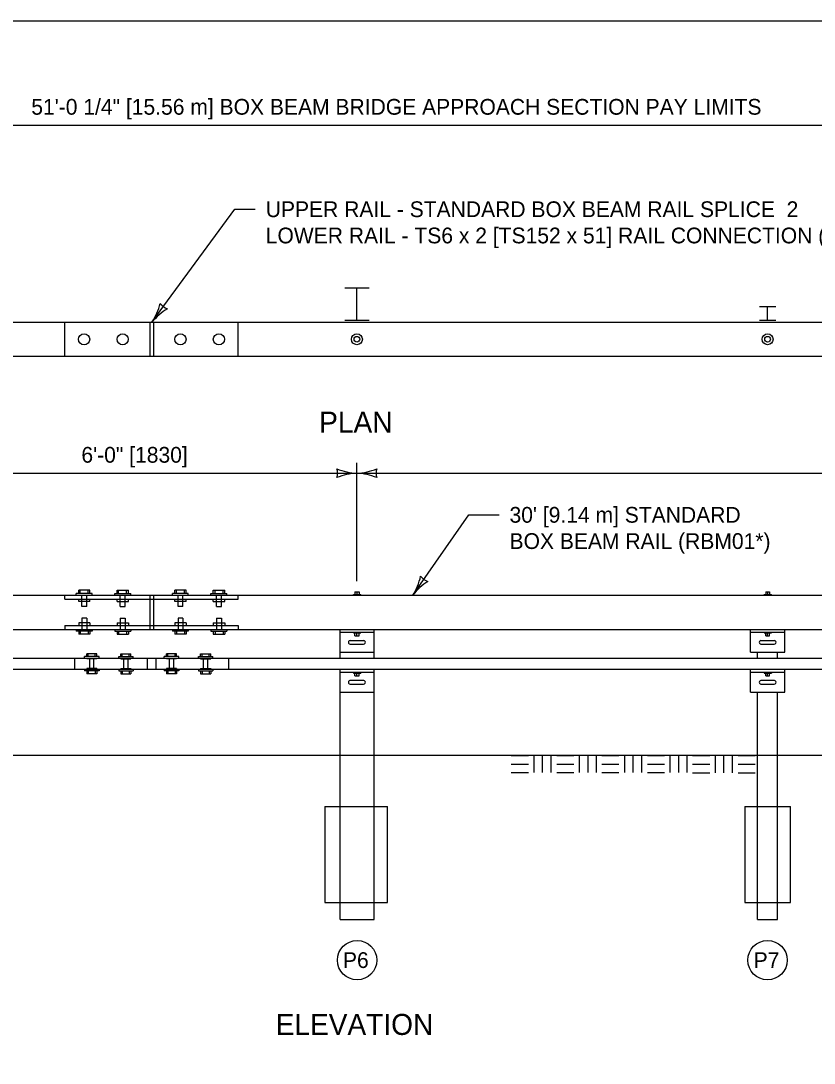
# Model space of a CAD drawing. Extents: x 49991.4 to 50021, y 49987.6 to 50011.4.
# Drawn here: x 50006.567 to 50009.589, y 49995.029 to 49998.999 of the extents above; entities that cross this region are included whole.
import ezdxf

# ---------------------------------------------------------------- set-up
doc = ezdxf.new("R2010")
doc.units = 0
for name, color, linetype in [('Level 1', 7, 'Continuous'), ('Level 2', 7, 'Continuous'), ('Level 3', 7, 'Continuous'), ('Level 4', 7, 'Continuous')]:
    doc.layers.add(name, color=color, linetype=linetype)

msp = doc.modelspace()

# ---------------------------------------------------------------- linework, layer by layer
at = {"layer": 'Level 1'}
for p, q in [((50007.8006, 49997.982), (50007.8938, 49997.982)), ((50007.8468, 49997.8587), (50007.8468, 49997.982)), ((50009.381, 49997.9109), (50009.4424, 49997.9109)), ((50009.4113, 49997.8587), (50009.4113, 49997.9109)), ((50001.743, 49997.8514), (50015.4519, 49997.8514)), ((50007.0582, 49997.8514), (50007.0582, 49997.7218)), ((50007.0716, 49997.8514), (50007.0716, 49997.7218)), ((50007.8006, 49997.8587), (50007.8938, 49997.8587)), ((50009.381, 49997.8587), (50009.4424, 49997.8587)), ((50001.743, 49997.7218), (50015.4519, 49997.7218)), ((50006.83, 49996.8312), (50006.7875, 49996.8312)), ((50006.7875, 49996.8181), (50006.7875, 49996.8312)), ((50006.7928, 49996.8181), (50006.7928, 49996.8312)), ((50006.8229, 49996.8181), (50006.8229, 49996.8312)), ((50006.83, 49996.8181), (50006.83, 49996.8312)), ((50006.9339, 49996.8312), (50006.9765, 49996.8312)), ((50006.9339, 49996.8181), (50006.9339, 49996.8312)), ((50006.9394, 49996.8181), (50006.9394, 49996.8312)), ((50006.9695, 49996.8181), (50006.9695, 49996.8312)), ((50006.9765, 49996.8181), (50006.9765, 49996.8312)), ((50007.1969, 49996.8312), (50007.1533, 49996.8312)), ((50007.1533, 49996.8181), (50007.1533, 49996.8312)), ((50007.1595, 49996.8181), (50007.1595, 49996.8312)), ((50007.1904, 49996.8181), (50007.1904, 49996.8312)), ((50007.1969, 49996.8181), (50007.1969, 49996.8312)), ((50007.2998, 49996.8181), (50007.2998, 49996.8312)), ((50007.2998, 49996.8312), (50007.3433, 49996.8312)), ((50007.3069, 49996.8181), (50007.3069, 49996.8312)), ((50007.337, 49996.8181), (50007.337, 49996.8312)), ((50007.3433, 49996.8181), (50007.3433, 49996.8312)), ((50002.0298, 49996.8116), (50015.4519, 49996.8116)), ((50006.8388, 49996.8181), (50006.7777, 49996.8181)), ((50006.7777, 49996.8116), (50006.7777, 49996.8181)), ((50006.8388, 49996.8116), (50006.8388, 49996.8181)), ((50006.9243, 49996.8181), (50006.9854, 49996.8181)), ((50006.9243, 49996.8116), (50006.9243, 49996.8181)), ((50006.9854, 49996.8116), (50006.9854, 49996.8181)), ((50007.0582, 49996.8126), (50007.0582, 49996.6812)), ((50007.0716, 49996.8126), (50007.0716, 49996.6812)), ((50007.2048, 49996.8181), (50007.1444, 49996.8181)), ((50007.1444, 49996.8116), (50007.1444, 49996.8181)), ((50007.2048, 49996.8116), (50007.2048, 49996.8181)), ((50007.2908, 49996.8181), (50007.3513, 49996.8181)), ((50007.2908, 49996.8126), (50007.2908, 49996.8181)), ((50007.3513, 49996.8116), (50007.3513, 49996.8181)), ((50007.7828, 49996.8116), (50007.9124, 49996.8116)), ((50007.8334, 49996.8144), (50007.8619, 49996.8144)), ((50007.8334, 49996.8116), (50007.8334, 49996.8144)), ((50007.8387, 49996.825), (50007.8556, 49996.825)), ((50007.8387, 49996.825), (50007.8387, 49996.8144)), ((50007.8468, 49996.825), (50007.8468, 49996.8144)), ((50007.8556, 49996.825), (50007.8556, 49996.8144)), ((50007.8619, 49996.8116), (50007.8619, 49996.8144)), ((50009.3793, 49996.8116), (50009.4441, 49996.8116)), ((50009.3981, 49996.8144), (50009.4266, 49996.8144)), ((50009.3981, 49996.8116), (50009.3981, 49996.8144)), ((50009.4041, 49996.825), (50009.4192, 49996.825)), ((50009.4041, 49996.825), (50009.4041, 49996.8144)), ((50009.4113, 49996.825), (50009.4113, 49996.8144)), ((50009.4192, 49996.825), (50009.4192, 49996.8144)), ((50009.4266, 49996.8116), (50009.4266, 49996.8144)), ((50002.0298, 49996.6812), (50015.4519, 49996.6812)), ((50006.7777, 49996.6812), (50006.7777, 49996.675)), ((50006.8388, 49996.675), (50006.7777, 49996.675)), ((50006.7875, 49996.675), (50006.7875, 49996.6634)), ((50006.7928, 49996.675), (50006.7928, 49996.6634)), ((50006.8229, 49996.675), (50006.8229, 49996.6634)), ((50006.83, 49996.675), (50006.83, 49996.6634)), ((50006.8388, 49996.6812), (50006.8388, 49996.675)), ((50006.9243, 49996.6812), (50006.9243, 49996.675)), ((50006.9243, 49996.675), (50006.9854, 49996.675)), ((50006.9339, 49996.675), (50006.9339, 49996.6634)), ((50006.9394, 49996.675), (50006.9394, 49996.6634)), ((50006.9695, 49996.675), (50006.9695, 49996.6634)), ((50006.9765, 49996.675), (50006.9765, 49996.6634)), ((50006.9854, 49996.6812), (50006.9854, 49996.675)), ((50007.1444, 49996.6812), (50007.1444, 49996.675)), ((50007.2048, 49996.675), (50007.1444, 49996.675)), ((50007.1533, 49996.675), (50007.1533, 49996.6634)), ((50007.1595, 49996.675), (50007.1595, 49996.6634)), ((50007.1904, 49996.675), (50007.1904, 49996.6634)), ((50007.1969, 49996.675), (50007.1969, 49996.6634)), ((50007.2048, 49996.6812), (50007.2048, 49996.675)), ((50007.2908, 49996.6812), (50007.2908, 49996.675)), ((50007.2908, 49996.675), (50007.3513, 49996.675)), ((50007.2998, 49996.675), (50007.2998, 49996.6634)), ((50007.3069, 49996.675), (50007.3069, 49996.6634)), ((50007.337, 49996.675), (50007.337, 49996.6634)), ((50007.3433, 49996.675), (50007.3433, 49996.6634)), ((50007.3513, 49996.6812), (50007.3513, 49996.675)), ((50007.7828, 49996.5719), (50007.7828, 49996.6812)), ((50007.7828, 49996.6705), (50007.9124, 49996.6705)), ((50007.8334, 49996.6705), (50007.8334, 49996.6679)), ((50007.8334, 49996.6679), (50007.8619, 49996.6679)), ((50007.8387, 49996.6572), (50007.8387, 49996.6679)), ((50007.8468, 49996.6572), (50007.8468, 49996.6679)), ((50007.8556, 49996.6572), (50007.8556, 49996.6679)), ((50007.8619, 49996.6705), (50007.8619, 49996.6679)), ((50007.9124, 49996.5719), (50007.9124, 49996.6812)), ((50009.3466, 49996.595), (50009.3466, 49996.6812)), ((50009.3466, 49996.6705), (50009.477, 49996.6705)), ((50009.3981, 49996.6705), (50009.3981, 49996.6679)), ((50009.3981, 49996.6679), (50009.4266, 49996.6679)), ((50009.4041, 49996.6572), (50009.4041, 49996.6679)), ((50009.4113, 49996.6572), (50009.4113, 49996.6679)), ((50009.4192, 49996.6572), (50009.4192, 49996.6679)), ((50009.4266, 49996.6705), (50009.4266, 49996.6679)), ((50009.477, 49996.595), (50009.477, 49996.6812)), ((50006.83, 49996.6634), (50006.7875, 49996.6634)), ((50006.9339, 49996.6634), (50006.9765, 49996.6634)), ((50007.1969, 49996.6634), (50007.1533, 49996.6634)), ((50007.2998, 49996.6634), (50007.3433, 49996.6634)), ((50007.8216, 49996.6389), (50007.8748, 49996.6389)), ((50007.8387, 49996.6572), (50007.8556, 49996.6572)), ((50009.3856, 49996.6385), (50009.438, 49996.6385)), ((50009.4041, 49996.6572), (50009.4192, 49996.6572)), ((50006.8566, 49996.5888), (50006.8184, 49996.5888)), ((50006.8184, 49996.5783), (50006.8184, 49996.5888)), ((50006.8229, 49996.5783), (50006.8229, 49996.5888)), ((50006.8505, 49996.5783), (50006.8505, 49996.5888)), ((50006.8566, 49996.5783), (50006.8566, 49996.5888)), ((50006.9481, 49996.5888), (50006.9862, 49996.5888)), ((50006.9481, 49996.5783), (50006.9481, 49996.5888)), ((50006.9534, 49996.5783), (50006.9534, 49996.5888)), ((50006.98, 49996.5783), (50006.98, 49996.5888)), ((50006.9862, 49996.5783), (50006.9862, 49996.5888)), ((50007.1603, 49996.5888), (50007.1222, 49996.5888)), ((50007.1222, 49996.5783), (50007.1222, 49996.5888)), ((50007.1267, 49996.5783), (50007.1267, 49996.5888)), ((50007.1542, 49996.5783), (50007.1542, 49996.5888)), ((50007.1603, 49996.5783), (50007.1603, 49996.5888)), ((50007.2518, 49996.5783), (50007.2518, 49996.5888)), ((50007.2518, 49996.5888), (50007.29, 49996.5888)), ((50007.2581, 49996.5783), (50007.2581, 49996.5888)), ((50007.2847, 49996.5783), (50007.2847, 49996.5888)), ((50007.29, 49996.5783), (50007.29, 49996.5888)), ((50007.7828, 49996.595), (50007.9124, 49996.595)), ((50007.8216, 49996.6253), (50007.8721, 49996.6253)), ((50009.3466, 49996.595), (50009.477, 49996.595)), ((50009.3731, 49996.5719), (50009.3731, 49996.595)), ((50009.3861, 49996.6253), (50009.4368, 49996.6253)), ((50009.4494, 49996.5719), (50009.4494, 49996.595)), ((50002.0449, 49996.5719), (50012.5032, 49996.5719)), ((50006.791, 49996.5719), (50007.0485, 49996.5719)), ((50006.8647, 49996.5783), (50006.8097, 49996.5783)), ((50006.8097, 49996.5719), (50006.8097, 49996.5783)), ((50006.8647, 49996.5719), (50006.8647, 49996.5783)), ((50006.9402, 49996.5783), (50006.9944, 49996.5783)), ((50006.9402, 49996.5719), (50006.9402, 49996.5783)), ((50006.9944, 49996.5719), (50006.9944, 49996.5783)), ((50007.0485, 49996.5719), (50007.0485, 49996.5294)), ((50007.0813, 49996.5719), (50007.3575, 49996.5719)), ((50007.0813, 49996.5719), (50007.0813, 49996.5294)), ((50007.1682, 49996.5783), (50007.1133, 49996.5783)), ((50007.1133, 49996.5719), (50007.1133, 49996.5783)), ((50007.1682, 49996.5719), (50007.1682, 49996.5783)), ((50007.2439, 49996.5783), (50007.298, 49996.5783)), ((50007.2439, 49996.5719), (50007.2439, 49996.5783)), ((50007.298, 49996.5719), (50007.298, 49996.5783)), ((50002.0449, 49996.5294), (50007.0485, 49996.5294)), ((50006.791, 49996.5294), (50007.0813, 49996.5294)), ((50006.8097, 49996.5294), (50006.8097, 49996.5231)), ((50006.8647, 49996.5231), (50006.8097, 49996.5231)), ((50006.8184, 49996.5231), (50006.8184, 49996.5124)), ((50006.8566, 49996.5124), (50006.8184, 49996.5124)), ((50006.8229, 49996.5231), (50006.8229, 49996.5124)), ((50006.8505, 49996.5231), (50006.8505, 49996.5124)), ((50006.8566, 49996.5231), (50006.8566, 49996.5124)), ((50006.8647, 49996.5294), (50006.8647, 49996.5231)), ((50006.9402, 49996.5294), (50006.9402, 49996.5231)), ((50006.9402, 49996.5231), (50006.9944, 49996.5231)), ((50006.9481, 49996.5231), (50006.9481, 49996.5124)), ((50006.9481, 49996.5124), (50006.9862, 49996.5124)), ((50006.9534, 49996.5231), (50006.9534, 49996.5124)), ((50006.98, 49996.5231), (50006.98, 49996.5124)), ((50006.9862, 49996.5231), (50006.9862, 49996.5124)), ((50006.9944, 49996.5294), (50006.9944, 49996.5231)), ((50007.0813, 49996.5294), (50007.3575, 49996.5294)), ((50007.0813, 49996.5294), (50012.5032, 49996.5294)), ((50007.1133, 49996.5294), (50007.1133, 49996.5231)), ((50007.1682, 49996.5231), (50007.1133, 49996.5231)), ((50007.1222, 49996.5231), (50007.1222, 49996.5124)), ((50007.1603, 49996.5124), (50007.1222, 49996.5124)), ((50007.1267, 49996.5231), (50007.1267, 49996.5124)), ((50007.1542, 49996.5231), (50007.1542, 49996.5124)), ((50007.1603, 49996.5231), (50007.1603, 49996.5124)), ((50007.1682, 49996.5294), (50007.1682, 49996.5231)), ((50007.2439, 49996.5294), (50007.2439, 49996.5231)), ((50007.2439, 49996.5231), (50007.298, 49996.5231)), ((50007.2518, 49996.5231), (50007.2518, 49996.5124)), ((50007.2518, 49996.5124), (50007.29, 49996.5124)), ((50007.2581, 49996.5231), (50007.2581, 49996.5124)), ((50007.2847, 49996.5231), (50007.2847, 49996.5124)), ((50007.29, 49996.5231), (50007.29, 49996.5124)), ((50007.298, 49996.5294), (50007.298, 49996.5231)), ((50007.7828, 49996.2026), (50007.7828, 49996.5294)), ((50007.7828, 49996.5187), (50007.9124, 49996.5187)), ((50007.8334, 49996.5187), (50007.8334, 49996.5152)), ((50007.8334, 49996.5152), (50007.8619, 49996.5152)), ((50007.8387, 49996.5044), (50007.8387, 49996.5152)), ((50007.8468, 49996.5044), (50007.8468, 49996.5152)), ((50007.8556, 49996.5044), (50007.8556, 49996.5152)), ((50007.8619, 49996.5187), (50007.8619, 49996.5152)), ((50007.9124, 49996.2026), (50007.9124, 49996.5294)), ((50009.3466, 49996.4422), (50009.3466, 49996.5294)), ((50009.3466, 49996.5187), (50009.477, 49996.5187)), ((50009.3981, 49996.5187), (50009.3981, 49996.5152)), ((50009.3981, 49996.5152), (50009.4266, 49996.5152)), ((50009.4041, 49996.5044), (50009.4041, 49996.5152)), ((50009.4113, 49996.5044), (50009.4113, 49996.5152)), ((50009.4192, 49996.5044), (50009.4192, 49996.5152)), ((50009.4266, 49996.5187), (50009.4266, 49996.5152)), ((50009.477, 49996.4422), (50009.477, 49996.5294)), ((50007.8202, 49996.4876), (50007.8734, 49996.4876)), ((50007.8216, 49996.4732), (50007.8721, 49996.4732)), ((50007.8387, 49996.5044), (50007.8556, 49996.5044)), ((50009.3856, 49996.4876), (50009.438, 49996.4876)), ((50009.3862, 49996.4732), (50009.4368, 49996.4732)), ((50009.4041, 49996.5044), (50009.4192, 49996.5044)), ((50007.7828, 49996.4422), (50007.9124, 49996.4422)), ((50009.3466, 49996.4422), (50009.477, 49996.4422)), ((50009.3731, 49996.2026), (50009.3731, 49996.4422)), ((50009.4494, 49996.2026), (50009.4494, 49996.4422)), ((50001.5626, 49996.2026), (50015.4519, 49996.2026)), ((50007.7828, 49996.2026), (50007.7828, 49996.2026)), ((50007.9124, 49996.2026), (50007.9124, 49996.2026)), ((50008.435, 49996.2009), (50008.5, 49996.2009)), ((50008.5217, 49996.1359), (50008.5217, 49996.2009)), ((50008.5542, 49996.1359), (50008.5542, 49996.2009)), ((50008.5867, 49996.1359), (50008.5867, 49996.2009)), ((50008.6083, 49996.2009), (50008.6734, 49996.2009)), ((50008.6951, 49996.1359), (50008.6951, 49996.2009)), ((50008.7275, 49996.1359), (50008.7275, 49996.2009)), ((50008.76, 49996.1359), (50008.76, 49996.2009)), ((50008.7803, 49996.2008), (50008.8453, 49996.2008)), ((50008.867, 49996.1358), (50008.867, 49996.2008)), ((50008.8995, 49996.1358), (50008.8995, 49996.2008)), ((50008.932, 49996.1358), (50008.932, 49996.2008)), ((50008.9536, 49996.2008), (50009.0187, 49996.2008)), ((50009.0404, 49996.1358), (50009.0404, 49996.2008)), ((50009.0728, 49996.1358), (50009.0728, 49996.2008)), ((50009.1053, 49996.1358), (50009.1053, 49996.2008)), ((50009.1259, 49996.2006), (50009.1909, 49996.2006)), ((50009.2126, 49996.1356), (50009.2126, 49996.2006)), ((50009.2451, 49996.1356), (50009.2451, 49996.2006)), ((50009.2776, 49996.1356), (50009.2776, 49996.2006)), ((50009.2992, 49996.2006), (50009.3643, 49996.2006)), ((50008.435, 49996.1684), (50008.5, 49996.1684)), ((50008.6083, 49996.1684), (50008.6734, 49996.1684)), ((50008.7803, 49996.1683), (50008.8453, 49996.1683)), ((50008.9536, 49996.1683), (50009.0187, 49996.1683)), ((50009.1259, 49996.1681), (50009.1909, 49996.1681)), ((50009.2992, 49996.1681), (50009.3643, 49996.1681)), ((50008.435, 49996.1359), (50008.5, 49996.1359)), ((50008.6083, 49996.1359), (50008.6734, 49996.1359)), ((50008.7803, 49996.1358), (50008.8453, 49996.1358)), ((50008.9536, 49996.1358), (50009.0187, 49996.1358)), ((50009.1259, 49996.1356), (50009.1909, 49996.1356)), ((50009.2992, 49996.1356), (50009.3643, 49996.1356))]:
    msp.add_line(p, q, dxfattribs=at)
msp.add_lwpolyline([(49999.3835, 49998.9992), (50016.7501, 49998.9992), (50016.7501, 49987.7988), (49999.3835, 49987.7988)], close=True, dxfattribs=at)
for centre, radius in [((50006.8079, 49997.7862), 0.0214), ((50006.9546, 49997.7862), 0.0214), ((50007.1746, 49997.7862), 0.0214), ((50007.3213, 49997.7862), 0.0214), ((50007.8468, 49997.7866), 0.0209), ((50007.8468, 49997.7866), 0.0109), ((50009.4113, 49997.7866), 0.0209), ((50009.4113, 49997.7866), 0.0109)]:
    msp.add_circle(centre, radius, dxfattribs=at)
for centre, start, end in [((50007.8212, 49996.6321), 86.0196, 273.9804), ((50007.8727, 49996.6321), 266.0196, 93.9804), ((50009.3857, 49996.6321), 86.0196, 273.9804), ((50009.4373, 49996.6321), 266.0196, 93.9804), ((50007.8212, 49996.48), 86.0196, 273.9804), ((50007.8727, 49996.48), 266.0196, 93.9804), ((50009.3857, 49996.48), 86.0196, 273.9804), ((50009.4373, 49996.48), 266.0196, 93.9804)]:
    msp.add_arc(centre, 0.00681, start, end, dxfattribs=at)
at = {"layer": 'Level 2'}
for centre in [(50007.8476, 49995.4216), (50009.4113, 49995.4216)]:
    msp.add_circle(centre, 0.075, dxfattribs=at)
at = {"layer": 'Level 3'}
for p, q in [((50001.5626, 49998.6017), (50014.9504, 49998.6017)), ((50007.0663, 49997.8514), (50007.3815, 49998.2816)), ((50007.3815, 49998.2816), (50007.4597, 49998.2816)), ((50007.8468, 49996.865), (50007.8468, 49997.3163)), ((50006.2831, 49997.2763), (50007.8468, 49997.2763)), ((50007.8468, 49997.2763), (50014.106, 49997.2763)), ((50008.06, 49996.8116), (50008.2732, 49997.1175)), ((50008.2733, 49997.1177), (50008.3883, 49997.1177))]:
    msp.add_line(p, q, dxfattribs=at)
for centre, radius, start, end in [((50006.8718, 49997.9797), 0.233, 326.5979, 345.8478), ((50007.2401, 49997.7127), 0.2223, 121.2266, 141.4102), ((50007.1421, 49997.9548), 0.0548, 215.9095, 251.6318), ((50007.856, 49997.4984), 0.2223, 247.456, 267.6395), ((50007.7186, 49997.2763), 0.0548, 342.1388, 17.8612), ((50007.8583, 49997.0436), 0.233, 92.8273, 112.0772), ((50007.8353, 49997.509), 0.233, 272.8273, 292.0772), ((50007.8376, 49997.0542), 0.2223, 67.456, 87.6395), ((50007.975, 49997.2763), 0.0548, 162.1388, 197.8612), ((50007.8625, 49996.9352), 0.233, 327.9514, 347.2012), ((50008.1333, 49996.9168), 0.0548, 217.2629, 252.9852), ((50008.237, 49996.6771), 0.2223, 122.5801, 142.7636)]:
    msp.add_arc(centre, radius, start, end, dxfattribs=at)
at = {"layer": 'Level 4'}
for p, q in [((50006.7342, 49997.7218), (50006.7342, 49997.8514)), ((50007.3947, 49997.7218), (50007.3947, 49997.8514)), ((50006.7342, 49996.7967), (50006.7342, 49996.8126)), ((50006.7342, 49996.7967), (50007.3947, 49996.7967)), ((50006.7875, 49996.7878), (50006.7875, 49996.7967)), ((50006.83, 49996.7878), (50006.7875, 49996.7878)), ((50006.799, 49996.769), (50006.799, 49996.8116)), ((50006.8177, 49996.769), (50006.8177, 49996.8116)), ((50006.83, 49996.7878), (50006.83, 49996.7967)), ((50006.9339, 49996.7878), (50006.9339, 49996.7967)), ((50006.9339, 49996.7878), (50006.9765, 49996.7878)), ((50006.9454, 49996.769), (50006.9454, 49996.8116)), ((50006.9642, 49996.769), (50006.9642, 49996.8116)), ((50006.9765, 49996.7878), (50006.9765, 49996.7967)), ((50007.1533, 49996.7878), (50007.1533, 49996.7967)), ((50007.1969, 49996.7878), (50007.1533, 49996.7878)), ((50007.1656, 49996.769), (50007.1656, 49996.8116)), ((50007.1834, 49996.769), (50007.1834, 49996.8116)), ((50007.1969, 49996.7878), (50007.1969, 49996.7967)), ((50007.2998, 49996.7878), (50007.2998, 49996.7967)), ((50007.2998, 49996.7878), (50007.3433, 49996.7878)), ((50007.3122, 49996.769), (50007.3122, 49996.8116)), ((50007.3309, 49996.769), (50007.3309, 49996.8116)), ((50007.3433, 49996.7878), (50007.3433, 49996.7967)), ((50007.3947, 49996.7967), (50007.3947, 49996.8126)), ((50006.8177, 49996.769), (50006.799, 49996.769)), ((50006.9454, 49996.769), (50006.9642, 49996.769)), ((50007.1834, 49996.769), (50007.1656, 49996.769)), ((50007.3122, 49996.769), (50007.3309, 49996.769)), ((50006.799, 49996.7238), (50006.799, 49996.6812)), ((50006.8177, 49996.7238), (50006.799, 49996.7238)), ((50006.8177, 49996.7238), (50006.8177, 49996.6812)), ((50006.9454, 49996.7238), (50006.9454, 49996.6812)), ((50006.9454, 49996.7238), (50006.9642, 49996.7238)), ((50006.9642, 49996.7238), (50006.9642, 49996.6812)), ((50007.1656, 49996.7238), (50007.1656, 49996.6812)), ((50007.1834, 49996.7238), (50007.1656, 49996.7238)), ((50007.1834, 49996.7238), (50007.1834, 49996.6812)), ((50007.3122, 49996.7238), (50007.3122, 49996.6812)), ((50007.3122, 49996.7238), (50007.3309, 49996.7238)), ((50007.3309, 49996.7238), (50007.3309, 49996.6812)), ((50006.7342, 49996.6964), (50007.3947, 49996.6964)), ((50006.7342, 49996.6964), (50006.7342, 49996.6812)), ((50006.83, 49996.7061), (50006.7875, 49996.7061)), ((50006.7875, 49996.7061), (50006.7875, 49996.6964)), ((50006.83, 49996.7061), (50006.83, 49996.6964)), ((50006.9339, 49996.7061), (50006.9765, 49996.7061)), ((50006.9339, 49996.7061), (50006.9339, 49996.6964)), ((50006.9765, 49996.7061), (50006.9765, 49996.6964)), ((50007.1969, 49996.7061), (50007.1533, 49996.7061)), ((50007.1533, 49996.7061), (50007.1533, 49996.6964)), ((50007.1969, 49996.7061), (50007.1969, 49996.6964)), ((50007.2998, 49996.7061), (50007.3433, 49996.7061)), ((50007.2998, 49996.7061), (50007.2998, 49996.6964)), ((50007.3433, 49996.7061), (50007.3433, 49996.6964)), ((50007.3947, 49996.6964), (50007.3947, 49996.6812)), ((50006.7714, 49996.5719), (50006.7714, 49996.5294)), ((50006.8184, 49996.5693), (50006.8184, 49996.5719)), ((50006.8566, 49996.5693), (50006.8184, 49996.5693)), ((50006.8229, 49996.5693), (50006.8229, 49996.5719)), ((50006.8292, 49996.532), (50006.8292, 49996.5693)), ((50006.8451, 49996.532), (50006.8451, 49996.5693)), ((50006.8505, 49996.5693), (50006.8505, 49996.5719)), ((50006.8566, 49996.5693), (50006.8566, 49996.5719)), ((50006.9481, 49996.5693), (50006.9481, 49996.5719)), ((50006.9481, 49996.5693), (50006.9862, 49996.5693)), ((50006.9534, 49996.5693), (50006.9534, 49996.5719)), ((50006.9587, 49996.532), (50006.9587, 49996.5693)), ((50006.9756, 49996.532), (50006.9756, 49996.5693)), ((50006.98, 49996.5693), (50006.98, 49996.5719)), ((50006.9862, 49996.5693), (50006.9862, 49996.5719)), ((50007.1222, 49996.5693), (50007.1222, 49996.5719)), ((50007.1603, 49996.5693), (50007.1222, 49996.5693)), ((50007.1267, 49996.5693), (50007.1267, 49996.5719)), ((50007.1328, 49996.532), (50007.1328, 49996.5693)), ((50007.1497, 49996.532), (50007.1497, 49996.5693)), ((50007.1542, 49996.5693), (50007.1542, 49996.5719)), ((50007.1603, 49996.5693), (50007.1603, 49996.5719)), ((50007.2518, 49996.5693), (50007.2518, 49996.5719)), ((50007.2518, 49996.5693), (50007.29, 49996.5693)), ((50007.2581, 49996.5693), (50007.2581, 49996.5719)), ((50007.2625, 49996.532), (50007.2625, 49996.5693)), ((50007.2793, 49996.532), (50007.2793, 49996.5693)), ((50007.2847, 49996.5693), (50007.2847, 49996.5719)), ((50007.29, 49996.5693), (50007.29, 49996.5719)), ((50007.3584, 49996.5719), (50007.3584, 49996.5294)), ((50006.8566, 49996.532), (50006.8184, 49996.532)), ((50006.8184, 49996.532), (50006.8184, 49996.5294)), ((50006.8229, 49996.532), (50006.8229, 49996.5294)), ((50006.8505, 49996.532), (50006.8505, 49996.5294)), ((50006.8566, 49996.532), (50006.8566, 49996.5294)), ((50006.9481, 49996.532), (50006.9862, 49996.532)), ((50006.9481, 49996.532), (50006.9481, 49996.5294)), ((50006.9534, 49996.532), (50006.9534, 49996.5294)), ((50006.98, 49996.532), (50006.98, 49996.5294)), ((50006.9862, 49996.532), (50006.9862, 49996.5294)), ((50007.1603, 49996.532), (50007.1222, 49996.532)), ((50007.1222, 49996.532), (50007.1222, 49996.5294)), ((50007.1267, 49996.532), (50007.1267, 49996.5294)), ((50007.1542, 49996.532), (50007.1542, 49996.5294)), ((50007.1603, 49996.532), (50007.1603, 49996.5294)), ((50007.2518, 49996.532), (50007.29, 49996.532)), ((50007.2518, 49996.532), (50007.2518, 49996.5294)), ((50007.2581, 49996.532), (50007.2581, 49996.5294)), ((50007.2847, 49996.532), (50007.2847, 49996.5294)), ((50007.29, 49996.532), (50007.29, 49996.5294)), ((50007.7828, 49995.5766), (50007.7828, 49996.2026)), ((50007.9124, 49995.5766), (50007.9124, 49996.2026)), ((50009.3731, 49995.5766), (50009.3731, 49996.2026)), ((50009.4494, 49995.5766), (50009.4494, 49996.2026)), ((50007.7251, 49996.0072), (50007.9639, 49996.0072)), ((50007.7251, 49996.0072), (50007.7251, 49995.6414)), ((50007.9639, 49995.6414), (50007.9639, 49996.0072)), ((50009.3243, 49996.0072), (50009.4984, 49996.0072)), ((50009.3243, 49996.0072), (50009.3243, 49995.6414)), ((50009.4984, 49995.6414), (50009.4984, 49996.0072)), ((50007.7251, 49995.6414), (50007.9639, 49995.6414)), ((50009.3243, 49995.6414), (50009.4984, 49995.6414)), ((50007.7828, 49995.5766), (50007.9124, 49995.5766)), ((50009.3731, 49995.5766), (50009.4494, 49995.5766))]:
    msp.add_line(p, q, dxfattribs=at)

# ---------------------------------------------------------------- texts
at = {"layer": 'Level 2'}
for s, height, p in [('51\'-0 1/4" [15.56 m] BOX BEAM BRIDGE APPROACH SECTION PAY LIMITS', 0.06, (50006.6066, 49998.6417)), ('UPPER RAIL - STANDARD BOX BEAM RAIL SPLICE  2', 0.06, (50007.4997, 49998.2517)), ('LOWER RAIL - TS6 x 2 [TS152 x 51] RAIL CONNECTION (SEE DETAIL)', 0.06, (50007.4997, 49998.1517)), ('PLAN', 0.08, (50007.7031, 49997.4306)), ('6\'-0" [1830]', 0.06, (50006.7975, 49997.3163)), ("30' [9.14 m] STANDARD ", 0.06, (50008.4283, 49997.0877)), ('BOX BEAM RAIL (RBM01*)', 0.06, (50008.4283, 49996.9877)), ('P6', 0.06, (50007.7938, 49995.3917)), ('P7', 0.06, (50009.3582, 49995.3917)), ('ELEVATION', 0.08, (50007.5374, 49995.1368))]:
    msp.add_text(s, height=height, dxfattribs=at).set_placement(p)

doc.saveas('drawing.dxf')
